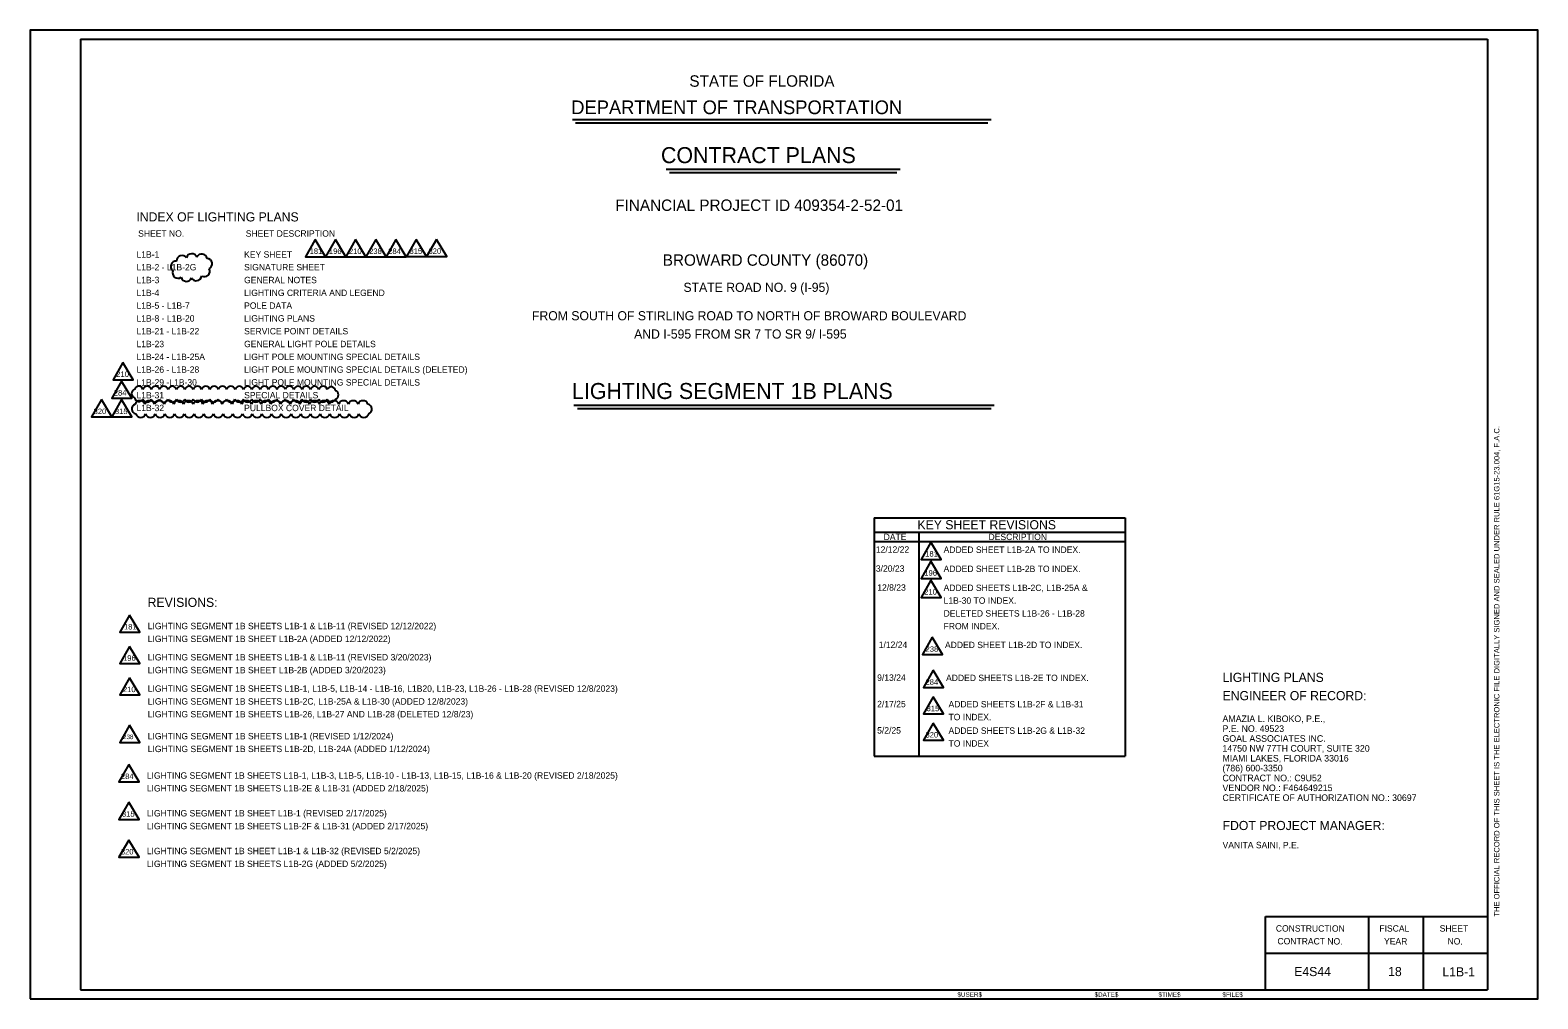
# Model space of a CAD drawing. Extents: x -818.6 to -802.1, y -2197.9 to -2175.
# Drawn here: x -818.56 to -802.06, y -2197.92 to -2187.32 of the extents above; entities that cross this region are included whole.
import ezdxf

# ---------------------------------------------------------------- set-up
doc = ezdxf.new("R2010")
doc.units = 0
for name, color, linetype in [('ActivePointCell_dp', 7, 'Continuous'), ('Cloud_dp', 7, 'Continuous'), ('PlotBorder_dp', 7, 'Continuous'), ('SheetBorder_dp', 7, 'Continuous'), ('SheetLines_dp', 7, 'Continuous'), ('SumBoxLines_dp', 7, 'Continuous'), ('TextLabel', 7, 'Continuous'), ('TextMinor', 7, 'Continuous'), ('TextMisc', 7, 'Continuous'), ('TextNotes', 7, 'Continuous'), ('TextShtNo', 7, 'Continuous'), ('TextTitle', 7, 'Continuous')]:
    doc.layers.add(name, color=color, linetype=linetype)

msp = doc.modelspace()

# ---------------------------------------------------------------- linework, layer by layer
at = {"layer": 'ActivePointCell_dp'}
msp.add_line((-802.614, -2187.419), (-802.614, -2187.419), dxfattribs=at)
at = {"layer": 'Cloud_dp'}
for points in [[(-815.443, -2189.61), (-815.551, -2189.798), (-815.33, -2189.798)], [(-815.222, -2189.61), (-815.33, -2189.798), (-815.109, -2189.798)], [(-815.002, -2189.61), (-815.109, -2189.798), (-814.889, -2189.798)], [(-814.781, -2189.61), (-814.889, -2189.798), (-814.668, -2189.798)], [(-814.56, -2189.61), (-814.667, -2189.798), (-814.447, -2189.798)], [(-814.339, -2189.609), (-814.446, -2189.797), (-814.226, -2189.797)], [(-814.118, -2189.609), (-814.226, -2189.797), (-814.005, -2189.797)], [(-817.548, -2190.956), (-817.656, -2191.145), (-817.435, -2191.145)], [(-817.563, -2191.159), (-817.671, -2191.347), (-817.45, -2191.347)], [(-817.783, -2191.362), (-817.891, -2191.55), (-817.671, -2191.55)], [(-817.563, -2191.362), (-817.671, -2191.55), (-817.45, -2191.55)], [(-808.706, -2192.922), (-808.814, -2193.11), (-808.593, -2193.11)], [(-808.706, -2193.13), (-808.814, -2193.318), (-808.593, -2193.318)], [(-808.706, -2193.338), (-808.814, -2193.526), (-808.593, -2193.526)], [(-817.475, -2193.719), (-817.583, -2193.907), (-817.362, -2193.907)], [(-808.691, -2193.963), (-808.799, -2194.151), (-808.578, -2194.151)], [(-817.475, -2194.062), (-817.583, -2194.25), (-817.362, -2194.25)], [(-808.68, -2194.324), (-808.787, -2194.512), (-808.567, -2194.512)], [(-817.475, -2194.405), (-817.583, -2194.593), (-817.362, -2194.593)], [(-808.68, -2194.613), (-808.787, -2194.801), (-808.567, -2194.801)], [(-817.475, -2194.924), (-817.583, -2195.113), (-817.362, -2195.113)], [(-808.68, -2194.901), (-808.787, -2195.089), (-808.567, -2195.089)], [(-817.485, -2195.356), (-817.593, -2195.544), (-817.372, -2195.544)], [(-817.485, -2195.768), (-817.593, -2195.957), (-817.372, -2195.957)], [(-817.485, -2196.181), (-817.593, -2196.369), (-817.372, -2196.369)]]:
    msp.add_lwpolyline(points, close=True, dxfattribs=at)
for centre, radius, start, end in [((-816.966, -2189.905), 0.0599, 86.9907, 231.9907), ((-816.902, -2189.845), 0.06, 35.4166, 180.4166), ((-816.795, -2189.825), 0.0599, 21.2778, 166.2778), ((-816.685, -2189.828), 0.0599, 9.9863, 154.9863), ((-816.632, -2189.877), 0.0599, 298.9542, 83.9542), ((-816.946, -2189.974), 0.0599, 159.4236, 304.4236), ((-816.854, -2190.008), 0.0599, 194.4381, 339.4381), ((-816.745, -2190.001), 0.0599, 207.5787, 352.5787), ((-816.657, -2189.957), 0.0599, 241.4449, 26.4449), ((-817.406, -2191.295), 0.0481, 107.5, 252.5), ((-817.375, -2191.264), 0.0481, 17.5, 162.5), ((-817.373, -2191.334), 0.048, 188.2189, 333.2189), ((-817.284, -2191.341), 0.0481, 197.5, 342.5), ((-817.283, -2191.264), 0.0481, 17.5, 162.5), ((-817.193, -2191.341), 0.0481, 197.5, 342.5), ((-817.192, -2191.264), 0.0481, 17.5, 162.5), ((-817.101, -2191.341), 0.0481, 197.5, 342.5), ((-817.1, -2191.264), 0.0481, 17.5, 162.5), ((-817.009, -2191.341), 0.0481, 197.5, 342.5), ((-817.008, -2191.264), 0.0481, 17.5, 162.5), ((-816.918, -2191.341), 0.0481, 197.5, 342.5), ((-816.917, -2191.264), 0.0481, 17.5, 162.5), ((-816.826, -2191.341), 0.0481, 197.5, 342.5), ((-816.825, -2191.264), 0.0481, 17.5, 162.5), ((-816.734, -2191.341), 0.0481, 197.5, 342.5), ((-816.733, -2191.264), 0.0481, 17.5, 162.5), ((-816.643, -2191.341), 0.0481, 197.5, 342.5), ((-816.642, -2191.264), 0.0481, 17.5, 162.5), ((-816.551, -2191.341), 0.0481, 197.5, 342.5), ((-816.55, -2191.264), 0.0481, 17.5, 162.5), ((-816.46, -2191.341), 0.0481, 197.5, 342.5), ((-816.458, -2191.264), 0.0481, 17.5, 162.5), ((-816.368, -2191.341), 0.0481, 197.5, 342.5), ((-816.367, -2191.264), 0.0481, 17.5, 162.5), ((-816.276, -2191.341), 0.0481, 197.5, 342.5), ((-816.275, -2191.264), 0.0481, 17.5, 162.5), ((-816.185, -2191.341), 0.0481, 197.5, 342.5), ((-816.183, -2191.264), 0.0481, 17.5, 162.5), ((-816.093, -2191.341), 0.0481, 197.5, 342.5), ((-816.092, -2191.264), 0.0481, 17.5, 162.5), ((-816.001, -2191.341), 0.0481, 197.5, 342.5), ((-816, -2191.264), 0.0481, 17.5, 162.5), ((-815.91, -2191.341), 0.0481, 197.5, 342.5), ((-815.908, -2191.264), 0.0481, 17.5, 162.5), ((-815.818, -2191.341), 0.0481, 197.5, 342.5), ((-815.817, -2191.264), 0.0481, 17.5, 162.5), ((-815.726, -2191.341), 0.0481, 197.5, 342.5), ((-815.725, -2191.264), 0.0481, 17.5, 162.5), ((-815.635, -2191.341), 0.0481, 197.5, 342.5), ((-815.633, -2191.264), 0.0481, 17.5, 162.5), ((-815.543, -2191.341), 0.0481, 197.5, 342.5), ((-815.542, -2191.264), 0.0481, 17.5, 162.5), ((-815.451, -2191.341), 0.0481, 197.5, 342.5), ((-815.45, -2191.264), 0.0481, 17.5, 162.5), ((-815.36, -2191.341), 0.0481, 197.5, 342.5), ((-815.358, -2191.264), 0.0481, 17.5, 162.5), ((-815.268, -2191.341), 0.0481, 197.5, 342.5), ((-815.27, -2191.271), 0.048, 8.2189, 153.2189), ((-815.237, -2191.31), 0.0481, 287.5, 72.5), ((-817.395, -2191.463), 0.0556, 112.2847, 257.2847), ((-817.363, -2191.429), 0.0557, 17.5, 162.5), ((-817.354, -2191.501), 0.0557, 197.5, 342.5), ((-817.257, -2191.429), 0.0557, 17.5, 162.5), ((-817.248, -2191.501), 0.0557, 197.5, 342.5), ((-817.151, -2191.429), 0.0557, 17.5, 162.5), ((-817.142, -2191.501), 0.0557, 197.5, 342.5), ((-817.045, -2191.429), 0.0557, 17.5, 162.5), ((-817.036, -2191.501), 0.0557, 197.5, 342.5), ((-816.939, -2191.429), 0.0557, 17.5, 162.5), ((-816.93, -2191.501), 0.0557, 197.5, 342.5), ((-816.832, -2191.429), 0.0557, 17.5, 162.5), ((-816.823, -2191.501), 0.0557, 197.5, 342.5), ((-816.726, -2191.429), 0.0557, 17.5, 162.5), ((-816.717, -2191.501), 0.0557, 197.5, 342.5), ((-816.62, -2191.429), 0.0557, 17.5, 162.5), ((-816.611, -2191.501), 0.0557, 197.5, 342.5), ((-816.514, -2191.429), 0.0557, 17.5, 162.5), ((-816.505, -2191.501), 0.0557, 197.5, 342.5), ((-816.408, -2191.429), 0.0557, 17.5, 162.5), ((-816.399, -2191.501), 0.0557, 197.5, 342.5), ((-816.301, -2191.429), 0.0557, 17.5, 162.5), ((-816.293, -2191.501), 0.0557, 197.5, 342.5), ((-816.195, -2191.429), 0.0557, 17.5, 162.5), ((-816.186, -2191.501), 0.0557, 197.5, 342.5), ((-816.089, -2191.429), 0.0557, 17.5, 162.5), ((-816.08, -2191.501), 0.0557, 197.5, 342.5), ((-815.983, -2191.429), 0.0557, 17.5, 162.5), ((-815.974, -2191.501), 0.0557, 197.5, 342.5), ((-815.877, -2191.429), 0.0557, 17.5, 162.5), ((-815.868, -2191.501), 0.0557, 197.5, 342.5), ((-815.77, -2191.429), 0.0557, 17.5, 162.5), ((-815.762, -2191.501), 0.0557, 197.5, 342.5), ((-815.664, -2191.429), 0.0557, 17.5, 162.5), ((-815.655, -2191.501), 0.0557, 197.5, 342.5), ((-815.558, -2191.429), 0.0557, 17.5, 162.5), ((-815.549, -2191.501), 0.0557, 197.5, 342.5), ((-815.452, -2191.429), 0.0557, 17.5, 162.5), ((-815.443, -2191.501), 0.0557, 197.5, 342.5), ((-815.346, -2191.429), 0.0557, 17.5, 162.5), ((-815.337, -2191.501), 0.0557, 197.5, 342.5), ((-815.239, -2191.429), 0.0557, 17.5, 162.5), ((-815.231, -2191.501), 0.0557, 197.5, 342.5), ((-815.133, -2191.429), 0.0557, 17.5, 162.5), ((-815.124, -2191.501), 0.0557, 197.5, 342.5), ((-815.027, -2191.429), 0.0557, 17.5, 162.5), ((-815.018, -2191.501), 0.0557, 197.5, 342.5), ((-814.921, -2191.429), 0.0557, 17.5, 162.5), ((-814.912, -2191.501), 0.0557, 197.5, 342.5), ((-814.88, -2191.466), 0.0556, 292.2847, 77.2847)]:
    msp.add_arc(centre, radius, start, end, dxfattribs=at)
at = {"layer": 'PlotBorder_dp'}
msp.add_lwpolyline([(-818.564, -2197.919), (-802.064, -2197.919), (-802.064, -2187.319), (-818.564, -2187.319)], close=True, dxfattribs=at)
at = {"layer": 'SheetBorder_dp'}
for p, q in [((-818.014, -2187.419), (-818.014, -2197.819)), ((-818.014, -2187.419), (-802.614, -2187.419)), ((-802.614, -2187.419), (-802.614, -2197.819)), ((-818.014, -2197.819), (-802.614, -2197.819))]:
    msp.add_line(p, q, dxfattribs=at)
at = {"layer": 'SheetLines_dp'}
for p, q in [((-805.044, -2197.019), (-802.614, -2197.019)), ((-805.044, -2197.819), (-805.044, -2197.019)), ((-803.914, -2197.819), (-803.914, -2197.019)), ((-803.314, -2197.819), (-803.314, -2197.019)), ((-805.044, -2197.419), (-802.614, -2197.419))]:
    msp.add_line(p, q, dxfattribs=at)
at = {"layer": 'SumBoxLines_dp'}
for p, q in [((-809.327, -2192.654), (-809.327, -2195.264)), ((-809.327, -2192.654), (-806.58, -2192.654)), ((-806.58, -2192.654), (-806.58, -2195.264)), ((-809.327, -2192.814), (-806.58, -2192.814)), ((-808.837, -2192.814), (-808.837, -2195.264)), ((-809.327, -2192.914), (-806.58, -2192.914)), ((-809.327, -2195.264), (-806.58, -2195.264))]:
    msp.add_line(p, q, dxfattribs=at)
at = {"layer": 'TextTitle'}
for p, q in [((-812.63, -2188.295), (-808.048, -2188.295)), ((-812.597, -2188.333), (-808.083, -2188.333)), ((-811.605, -2188.84), (-809.044, -2188.84)), ((-811.566, -2188.878), (-809.077, -2188.878)), ((-812.614, -2191.421), (-808.015, -2191.421)), ((-812.575, -2191.459), (-808.047, -2191.459))]:
    msp.add_line(p, q, dxfattribs=at)

# ---------------------------------------------------------------- texts
at = {"layer": 'Cloud_dp'}
for s, height, p in [('181', 0.06, (-815.505, -2189.768)), ('196', 0.06, (-815.294, -2189.768)), ('210', 0.06, (-815.075, -2189.768)), ('238', 0.06, (-814.854, -2189.768)), ('284', 0.06, (-814.645, -2189.768)), ('315', 0.06, (-814.412, -2189.767)), ('320', 0.06, (-814.204, -2189.767)), ('210', 0.06, (-817.621, -2191.114)), ('284', 0.06, (-817.648, -2191.317)), ('320', 0.06, (-817.869, -2191.52)), ('315', 0.06, (-817.636, -2191.52)), ('181', 0.06, (-808.768, -2193.079)), ('196', 0.06, (-808.778, -2193.288)), ('210', 0.06, (-808.779, -2193.496)), ('181', 0.06, (-817.537, -2193.877)), ('196', 0.06, (-817.547, -2194.22)), ('238', 0.06, (-808.764, -2194.121)), ('284', 0.06, (-808.765, -2194.482)), ('210', 0.06, (-817.548, -2194.563)), ('315', 0.06, (-808.753, -2194.771)), ('238', 0.05, (-817.548, -2195.077)), ('320', 0.06, (-808.765, -2195.059)), ('284', 0.06, (-817.57, -2195.514)), ('315', 0.06, (-817.559, -2195.926)), ('320', 0.06, (-817.571, -2196.339))]:
    msp.add_text(s, height=height, rotation=0, dxfattribs=at).set_placement(p)
at = {"layer": 'TextLabel'}
for s, height, p in [('FINANCIAL PROJECT ID 409354-2-52-01', 0.125, (-812.16, -2189.297)), ('INDEX OF LIGHTING PLANS', 0.1, (-817.401, -2189.412)), ('L1B-1', 0.07, (-817.4, -2189.808)), ('L1B-2 - L1B-2G', 0.07, (-817.4, -2189.948)), ('SIGNATURE SHEET', 0.07, (-816.222, -2189.948)), ('KEY SHEET', 0.07, (-816.222, -2189.808)), ('BROWARD COUNTY (86070)', 0.125, (-811.64, -2189.897)), ('L1B-3', 0.07, (-817.4, -2190.088)), ('GENERAL NOTES', 0.07, (-816.222, -2190.088)), ('L1B-4', 0.07, (-817.4, -2190.228)), ('LIGHTING CRITERIA AND LEGEND', 0.07, (-816.222, -2190.228)), ('STATE ROAD NO. 9 (I-95)', 0.1, (-811.414, -2190.183)), ('L1B-5 - L1B-7', 0.07, (-817.4, -2190.368)), ('POLE DATA', 0.07, (-816.222, -2190.368)), ('L1B-8 - L1B-20', 0.07, (-817.4, -2190.508)), ('LIGHTING PLANS', 0.07, (-816.222, -2190.508)), ('FROM SOUTH OF STIRLING ROAD TO NORTH OF BROWARD BOULEVARD', 0.1, (-813.072, -2190.494)), ('L1B-21 - L1B-22', 0.07, (-817.4, -2190.648)), ('SERVICE POINT DETAILS', 0.07, (-816.222, -2190.648)), ('AND I-595 FROM SR 7 TO SR 9/ I-595', 0.1, (-811.954, -2190.694)), ('L1B-23', 0.07, (-817.4, -2190.788)), ('L1B-24 - L1B-25A', 0.07, (-817.4, -2190.928)), ('GENERAL LIGHT POLE DETAILS', 0.07, (-816.222, -2190.788)), ('LIGHT POLE MOUNTING SPECIAL DETAILS', 0.07, (-816.222, -2190.928)), ('L1B-26 - L1B-28', 0.07, (-817.4, -2191.068)), ('LIGHT POLE MOUNTING SPECIAL DETAILS (DELETED)', 0.07, (-816.222, -2191.068)), ('L1B-29 -L1B-30', 0.07, (-817.4, -2191.208)), ('LIGHT POLE MOUNTING SPECIAL DETAILS', 0.07, (-816.222, -2191.208)), ('L1B-31', 0.07, (-817.4, -2191.348)), ('SPECIAL DETAILS', 0.07, (-816.222, -2191.348)), ('L1B-32', 0.07, (-817.4, -2191.488)), ('PULLBOX COVER DETAIL', 0.07, (-816.222, -2191.488)), ('KEY SHEET REVISIONS', 0.1, (-808.853, -2192.781)), ('REVISIONS:', 0.1, (-817.278, -2193.63)), ('LIGHTING PLANS', 0.1, (-805.514, -2194.451)), ('ENGINEER OF RECORD:', 0.1, (-805.514, -2194.651)), ('AMAZIA L. KIBOKO, P.E.,', 0.07202, (-805.515, -2194.89)), ('P.E. NO. 49523', 0.07202, (-805.515, -2194.998)), ('GOAL ASSOCIATES INC. ', 0.07202, (-805.515, -2195.106)), ('14750 NW 77TH COURT, SUITE 320', 0.07202, (-805.515, -2195.214)), ('MIAMI LAKES, FLORIDA 33016', 0.07202, (-805.515, -2195.322)), ('CONTRACT NO.: C9U52', 0.07202, (-805.515, -2195.538)), ('(786) 600-3350', 0.07202, (-805.515, -2195.43)), ('VENDOR NO.: F464649215', 0.07202, (-805.515, -2195.646)), ('CERTIFICATE OF AUTHORIZATION NO.: 30697', 0.07202, (-805.515, -2195.754)), ('E4S44', 0.1, (-804.73, -2197.67)), ('18', 0.1, (-803.702, -2197.67))]:
    msp.add_text(s, height=height, dxfattribs=at).set_placement(p)
at = {"layer": 'TextMinor'}
for s, height, p in [('12/12/22', 0.07, (-809.308, -2193.037)), ('ADDED SHEET L1B-2A TO INDEX.', 0.07, (-808.567, -2193.039)), ('3/20/23', 0.07, (-809.308, -2193.245)), ('ADDED SHEET L1B-2B TO INDEX.', 0.07, (-808.567, -2193.248)), ('12/8/23', 0.07, (-809.293, -2193.453)), ('ADDED SHEETS L1B-2C, L1B-25A & ', 0.07, (-808.567, -2193.456)), ('L1B-30 TO INDEX.', 0.07, (-808.567, -2193.596)), ('DELETED SHEETS L1B-26 - L1B-28 ', 0.07, (-808.567, -2193.736)), ('FROM INDEX.', 0.07, (-808.567, -2193.876)), ('1/12/24', 0.07, (-809.277, -2194.079)), ('ADDED SHEET L1B-2D TO INDEX.', 0.07, (-808.552, -2194.081)), ('9/13/24', 0.07, (-809.294, -2194.439)), ('ADDED SHEETS L1B-2E TO INDEX.', 0.07, (-808.54, -2194.442)), ('2/17/25', 0.07, (-809.294, -2194.728)), ('ADDED SHEETS L1B-2F & L1B-31      ', 0.07, (-808.513, -2194.73)), ('TO INDEX.', 0.07, (-808.513, -2194.87)), ('5/2/25', 0.07, (-809.294, -2195.016)), ('ADDED SHEETS L1B-2G & L1B-32      ', 0.07, (-808.513, -2195.019)), ('TO INDEX', 0.07, (-808.513, -2195.159)), ('$USER$', 0.05, (-808.415, -2197.897))]:
    msp.add_text(s, height=height, dxfattribs=at).set_placement(p)
for s, p in [('$DATE$', (-806.915, -2197.897)), ('$TIME$', (-806.215, -2197.897)), ('$FILE$', (-805.515, -2197.897))]:
    msp.add_text(s, height=0.05, rotation=360, dxfattribs=at).set_placement(p)
at = {"layer": 'TextMisc'}
msp.add_text('THE OFFICIAL RECORD OF THIS SHEET IS THE ELECTRONIC FILE DIGITALLY SIGNED AND SEALED UNDER RULE 61G15-23.004, F.A.C.', height=0.06, rotation=90, dxfattribs=at).set_placement((-802.484, -2197.019))
at = {"layer": 'TextNotes'}
for s, height, p in [('SHEET NO.', 0.07, (-817.382, -2189.579)), ('SHEET DESCRIPTION', 0.07, (-816.204, -2189.579)), ('DATE', 0.07, (-809.223, -2192.899)), ('DESCRIPTION', 0.07, (-808.075, -2192.899)), ('LIGHTING SEGMENT 1B SHEETS L1B-1 & L1B-11 (REVISED 12/12/2022)', 0.06998, (-817.277, -2193.874)), ('LIGHTING SEGMENT 1B SHEET L1B-2A (ADDED 12/12/2022)', 0.06998, (-817.277, -2194.014)), ('LIGHTING SEGMENT 1B SHEETS L1B-1 & L1B-11 (REVISED 3/20/2023)', 0.06998, (-817.277, -2194.216)), ('LIGHTING SEGMENT 1B SHEET L1B-2B (ADDED 3/20/2023)', 0.06998, (-817.277, -2194.356)), ('LIGHTING SEGMENT 1B SHEETS L1B-1, L1B-5, L1B-14 - L1B-16, L1B20, L1B-23, L1B-26 - L1B-28 (REVISED 12/8/2023)', 0.069982, (-817.277, -2194.559)), ('LIGHTING SEGMENT 1B SHEETS L1B-2C, L1B-25A & L1B-30 (ADDED 12/8/2023)', 0.06998, (-817.277, -2194.699)), ('LIGHTING SEGMENT 1B SHEETS L1B-26, L1B-27 AND L1B-28 (DELETED 12/8/23)', 0.06998, (-817.277, -2194.839)), ('LIGHTING SEGMENT 1B SHEETS L1B-1 (REVISED 1/12/2024)', 0.06998, (-817.277, -2195.079)), ('LIGHTING SEGMENT 1B SHEETS L1B-2D, L1B-24A (ADDED 1/12/2024)', 0.06998, (-817.277, -2195.219)), ('LIGHTING SEGMENT 1B SHEETS L1B-1, L1B-3, L1B-5, L1B-10 - L1B-13, L1B-15, L1B-16 & L1B-20 (REVISED 2/18/2025)', 0.069982, (-817.287, -2195.51)), ('LIGHTING SEGMENT 1B SHEETS L1B-2E & L1B-31 (ADDED 2/18/2025)', 0.06998, (-817.287, -2195.65)), ('LIGHTING SEGMENT 1B SHEET L1B-1 (REVISED 2/17/2025)', 0.06998, (-817.287, -2195.923)), ('FDOT PROJECT MANAGER:', 0.1, (-805.514, -2196.072)), ('LIGHTING SEGMENT 1B SHEETS L1B-2F & L1B-31 (ADDED 2/17/2025)', 0.06998, (-817.287, -2196.063)), ('LIGHTING SEGMENT 1B SHEET L1B-1 & L1B-32 (REVISED 5/2/2025)', 0.06998, (-817.287, -2196.336)), ('VANITA SAINI, P.E.', 0.07, (-805.514, -2196.271)), ('LIGHTING SEGMENT 1B SHEETS L1B-2G (ADDED 5/2/2025)', 0.06998, (-817.287, -2196.476))]:
    msp.add_text(s, height=height, dxfattribs=at).set_placement(p)
for s, p in [('CONSTRUCTION', (-804.931, -2197.183)), ('FISCAL', (-803.798, -2197.183)), ('SHEET', (-803.138, -2197.183)), ('CONTRACT NO.', (-804.913, -2197.323)), ('YEAR', (-803.747, -2197.324)), ('NO.', (-803.052, -2197.324))]:
    msp.add_text(s, height=0.07, rotation=359.8607, dxfattribs=at).set_placement(p)
at = {"layer": 'TextShtNo'}
msp.add_text('L1B-1', height=0.1, dxfattribs=at).set_placement((-803.108, -2197.673))
at = {"layer": 'TextTitle'}
for s, height, p in [('STATE OF FLORIDA', 0.125, (-811.349, -2187.938)), ('DEPARTMENT OF TRANSPORTATION', 0.15, (-812.642, -2188.238)), ('CONTRACT PLANS', 0.175, (-811.66, -2188.774)), ('LIGHTING SEGMENT 1B PLANS', 0.175, (-812.634, -2191.355))]:
    msp.add_text(s, height=height, dxfattribs=at).set_placement(p)

doc.saveas('drawing.dxf')
